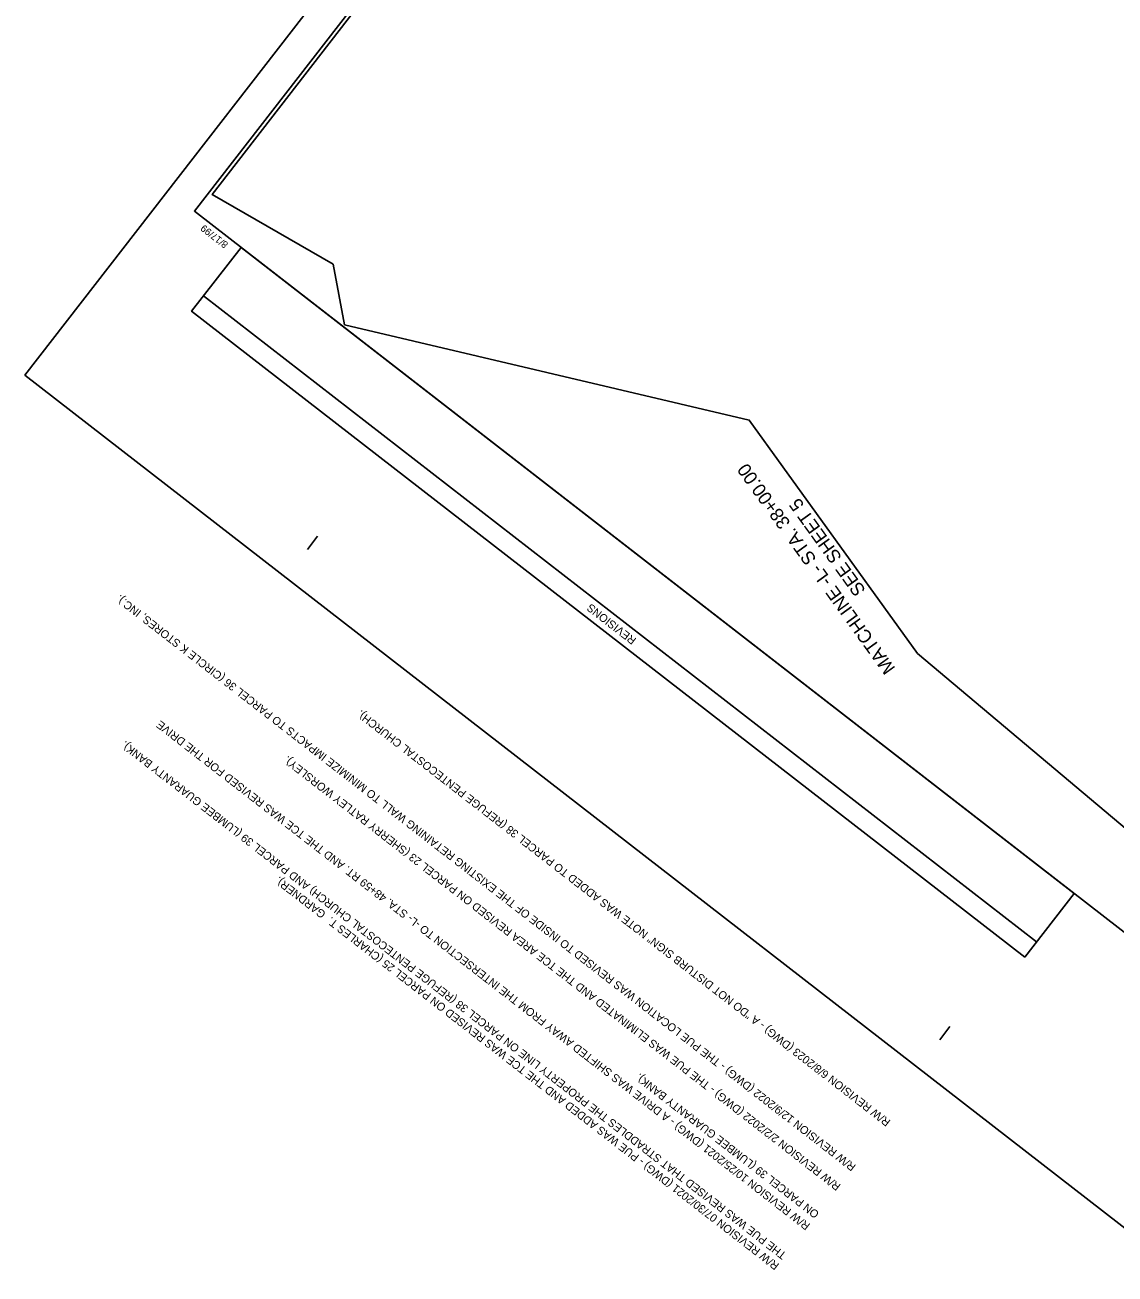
# Model space of a CAD drawing. Extents: x 2013373 to 2015284, y 444618 to 446636.
# Drawn here: x 2013373 to 2014190, y 444618 to 445555 of the extents above; entities that cross this region are included whole.
import ezdxf

# ---------------------------------------------------------------- set-up
doc = ezdxf.new("R2010")
doc.units = 0
for name, color, linetype in [('Old_Level_2', 7, 'Continuous'), ('Prop Conc 5in Monolithic Keyed In Island', 7, 'Continuous'), ('Prop Dimension Text', 7, 'Continuous'), ('Prop Horizontal Alignment', 7, 'Continuous'), ('Prop Horizontal Alignment Tick Label', 7, 'Continuous'), ('Prop Noise Wall', 7, 'Continuous'), ('Prop North Arrow NAD83 for Plan Sheets CELL', 7, 'Continuous')]:
    doc.layers.add(name, color=color, linetype=linetype)

msp = doc.modelspace()

# ---------------------------------------------------------------- linework, layer by layer
at = {"layer": 'Prop Conc 5in Monolithic Keyed In Island'}
msp.add_lwpolyline([(2014241.91, 444618.03), (2015283.73, 445961.39), (2014414.5, 446635.51), (2013372.67, 445292.15)], close=True, dxfattribs=at)
at = {"layer": 'Prop Dimension Text'}
msp.add_line((2014041.96, 445083.42), (2013915.76, 445258.44), dxfattribs=at)
at = {"layer": 'Prop Horizontal Alignment'}
for p, q in [((2013584.49, 445161.42), (2013592.15, 445171.29)), ((2014058.62, 444793.71), (2014066.28, 444803.59))]:
    msp.add_line(p, q, dxfattribs=at)
msp.add_lwpolyline([(2014418.93, 446600.43), (2013499.68, 445415.12), (2014329.4, 444771.64), (2015248.65, 445956.96)], close=True, dxfattribs=at)
at = {"layer": 'Prop Horizontal Alignment Tick Label'}
msp.add_line((2014131.31, 444867.05), (2013506.53, 445351.59), dxfattribs=at)
msp.add_lwpolyline([(2014122.39, 444855.55), (2013497.61, 445340.09), (2013534.72, 445387.94), (2014159.5, 444903.4)], close=True, dxfattribs=at)
at = {"layer": 'Prop Noise Wall'}
msp.add_lwpolyline([(2014144.54, 446243.36), (2013513.08, 445427.57), (2013603.78, 445375.37), (2013612.37, 445329.9), (2013915.76, 445258.44), (2014041.96, 445083.42), (2014361.11, 444814.86), (2015247.36, 445957.62), (2014564.18, 446487.45), (2014441.6, 446328.92), (2014350.52, 446399.67), (2014197.18, 446202.42)], close=True, dxfattribs=at)

# ---------------------------------------------------------------- texts
at = {"layer": 'Old_Level_2'}
for s, p in [('R/W REVISION 12/9/2022 (DWG) - THE PUE LOCATION WAS REVISED TO INSIDE OF THE EXISTING RETAINING WALL TO MINIMIZE IMPACTS TO PARCEL 36 (CIRCLE K STORES, INC.).', (2013996.27, 444699.47)), ('R/W REVISION 6/8/2023 (DWG) - A "DO NOT DISTURB SIGN" NOTE WAS ADDED TO PARCEL 38 (REFUGE PENTECOSTAL CHURCH).', (2014022.26, 444733)), ('R/W REVISION 10/25/2021 (DWG) - A DRIVE WAS SHIFTED AWAY FROM THE INTERSECTION TO -L- STA. 48+59 RT. AND THE TCE WAS REVISED FOR THE DRIVE', (2013961.94, 444655.22)), ('THE PUE WAS REVISED THAT STRADDLES THE PROPERTY LINE ON PARCEL 38 (REFUGE PENTECOSTAL CHURCH) AND PARCEL 39 (LUMBEE GUARANTY BANK). ', (2013944.15, 444633.26)), ('R/W REVISION 2/2/2022 (DWG) - THE PUE WAS ELIMINATED AND THE TCE AREA REVISED ON PARCEL 23 (SHERRY RATLEY WORSLEY).', (2013984.91, 444684.83)), ('R/W REVISION 07/30/2021 (DWG) - PUE WAS ADDED AND THE TCE WAS REVISED ON PARCEL 25 (CHARLES T.  GARDNER). ', (2013938.76, 444625.32)), ('ON PARCEL 39 (LUMBEE GUARANTY BANK).', (2013968.73, 444663.97))]:
    msp.add_text(s, height=6, rotation=142.2051, dxfattribs=at).set_placement(p)
at = {"layer": 'Prop Horizontal Alignment'}
msp.add_text('8/17/99', height=5.25, rotation=142.2051, dxfattribs=at).set_placement((2013525.5, 445390.98))
at = {"layer": 'Prop Horizontal Alignment Tick Label'}
msp.add_text('REVISIONS', height=6, rotation=142.2051, dxfattribs=at).set_placement((2013831.59, 445094.37))
at = {"layer": 'Prop North Arrow NAD83 for Plan Sheets CELL'}
for s, p in [('MATCHLINE -L- STA. 38+00.00', (2014025.76, 445072.32)), ('SEE SHEET 5', (2014003.55, 445130.91))]:
    msp.add_text(s, height=10, rotation=125.79448, dxfattribs=at).set_placement(p)

doc.saveas('drawing.dxf')
